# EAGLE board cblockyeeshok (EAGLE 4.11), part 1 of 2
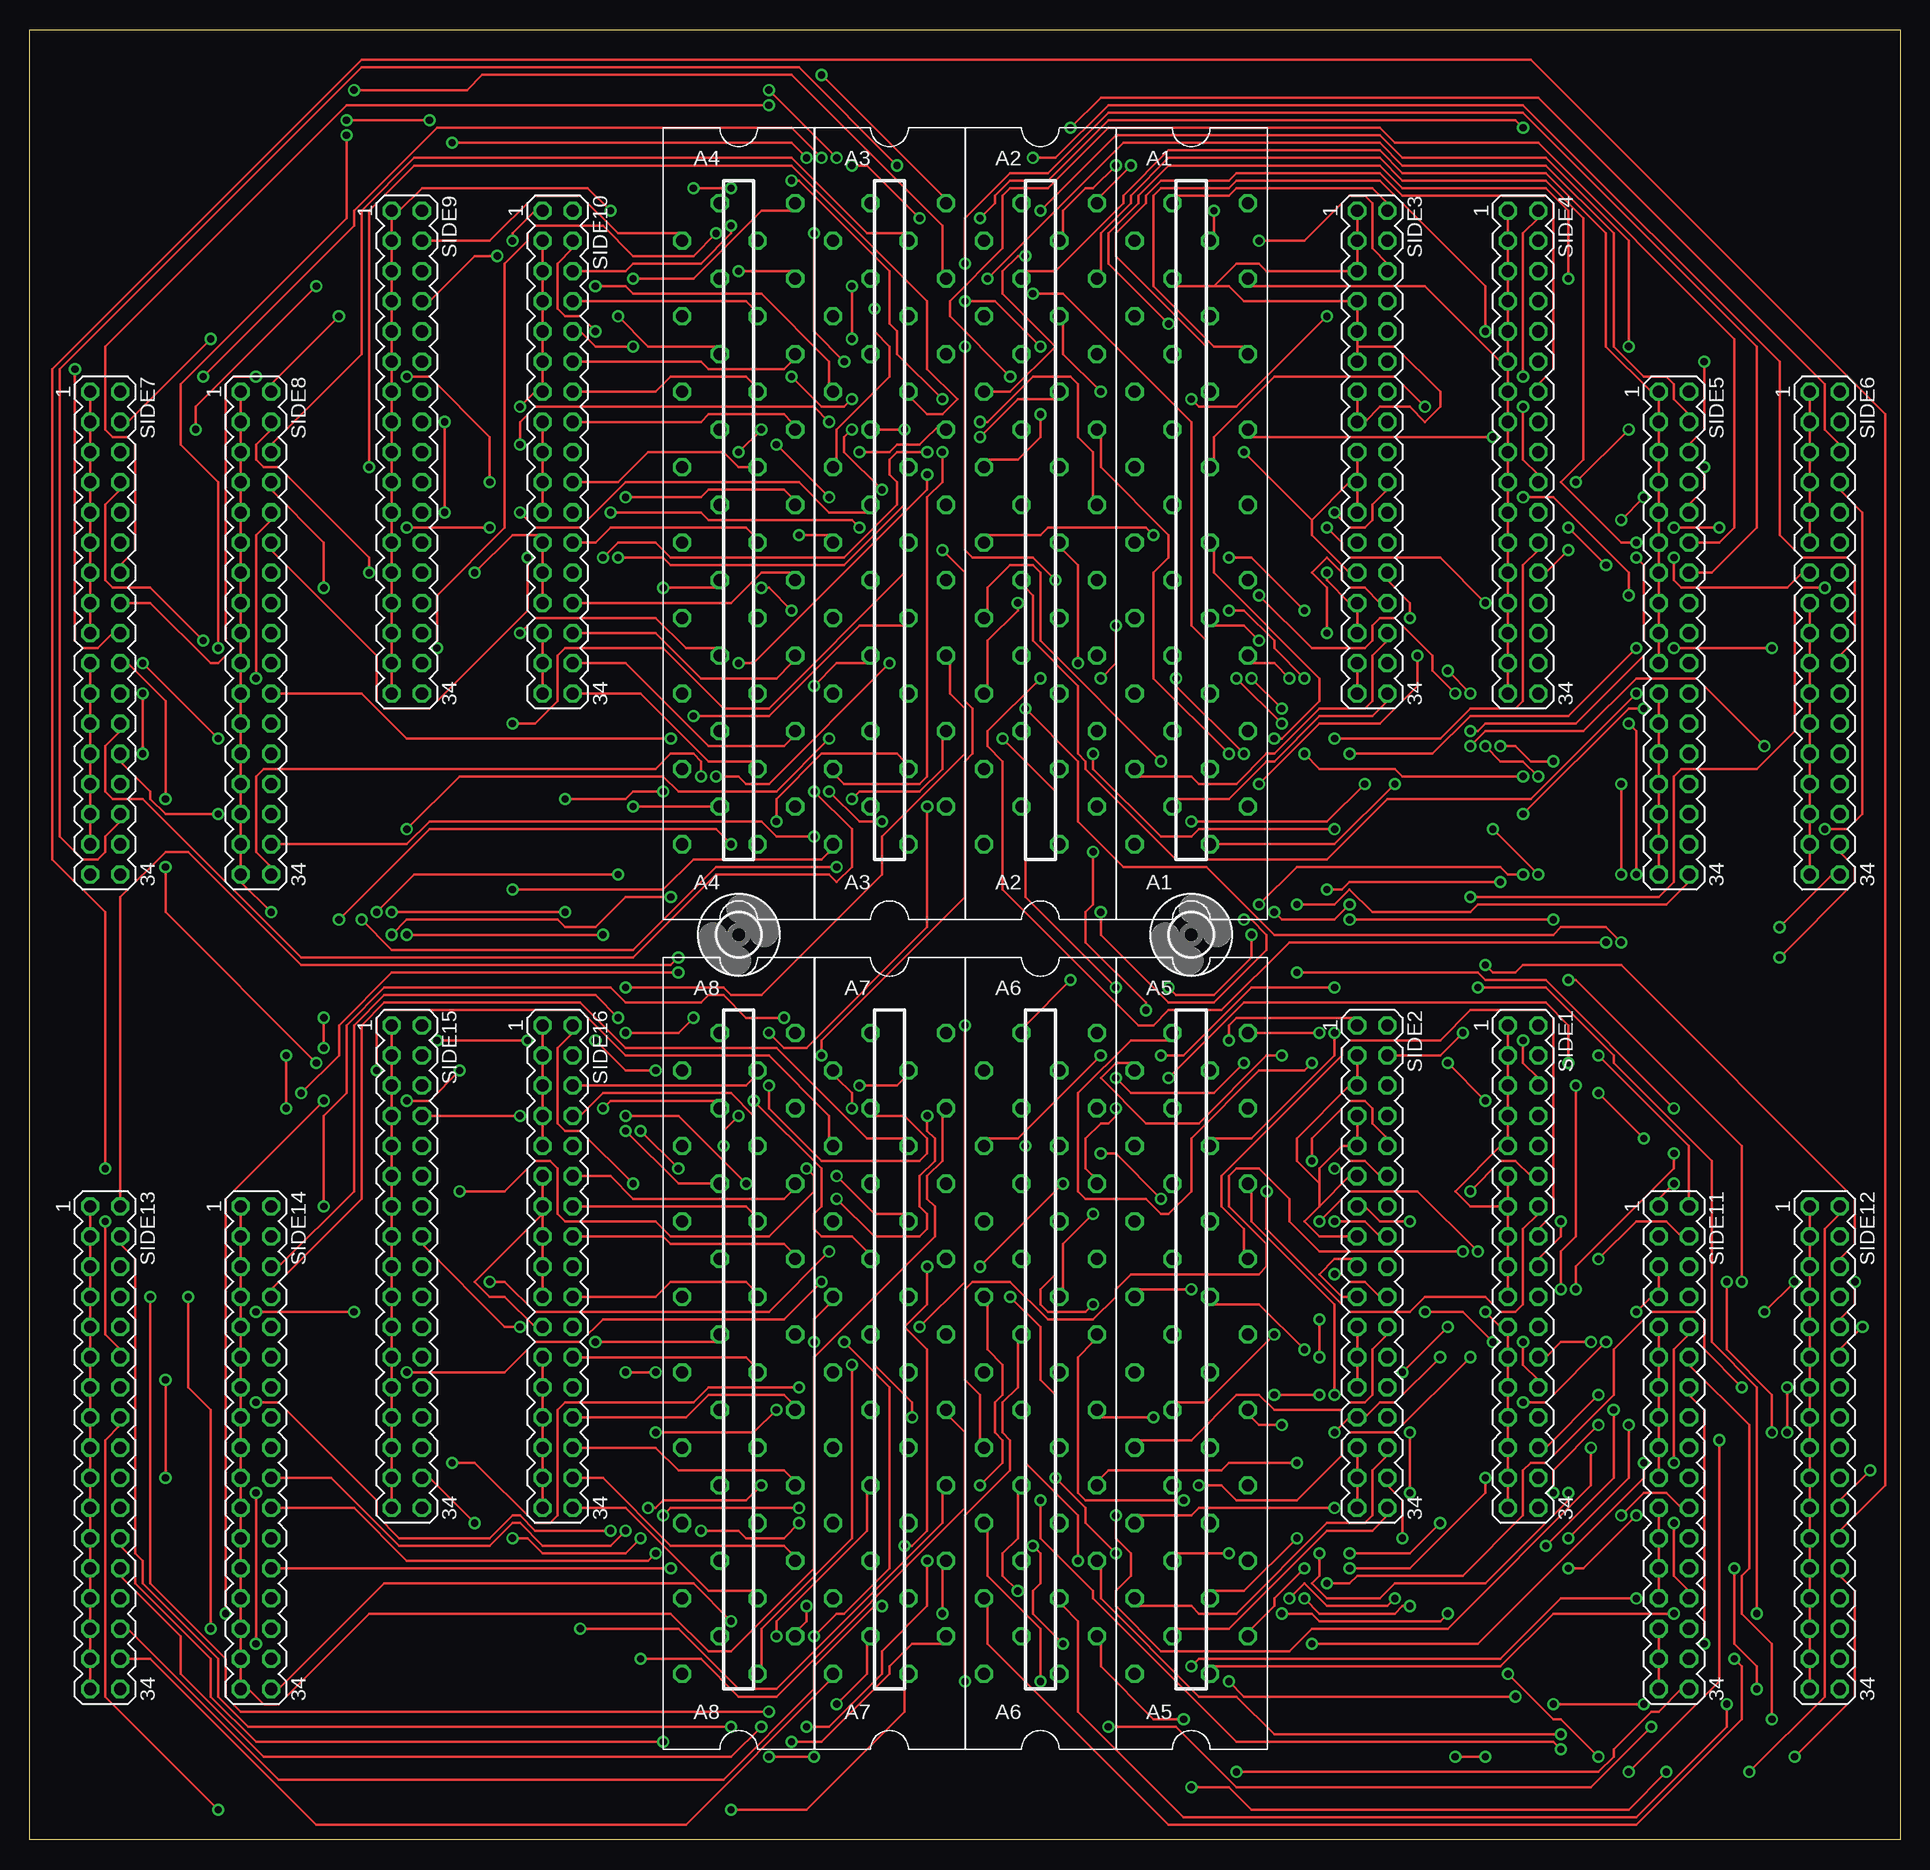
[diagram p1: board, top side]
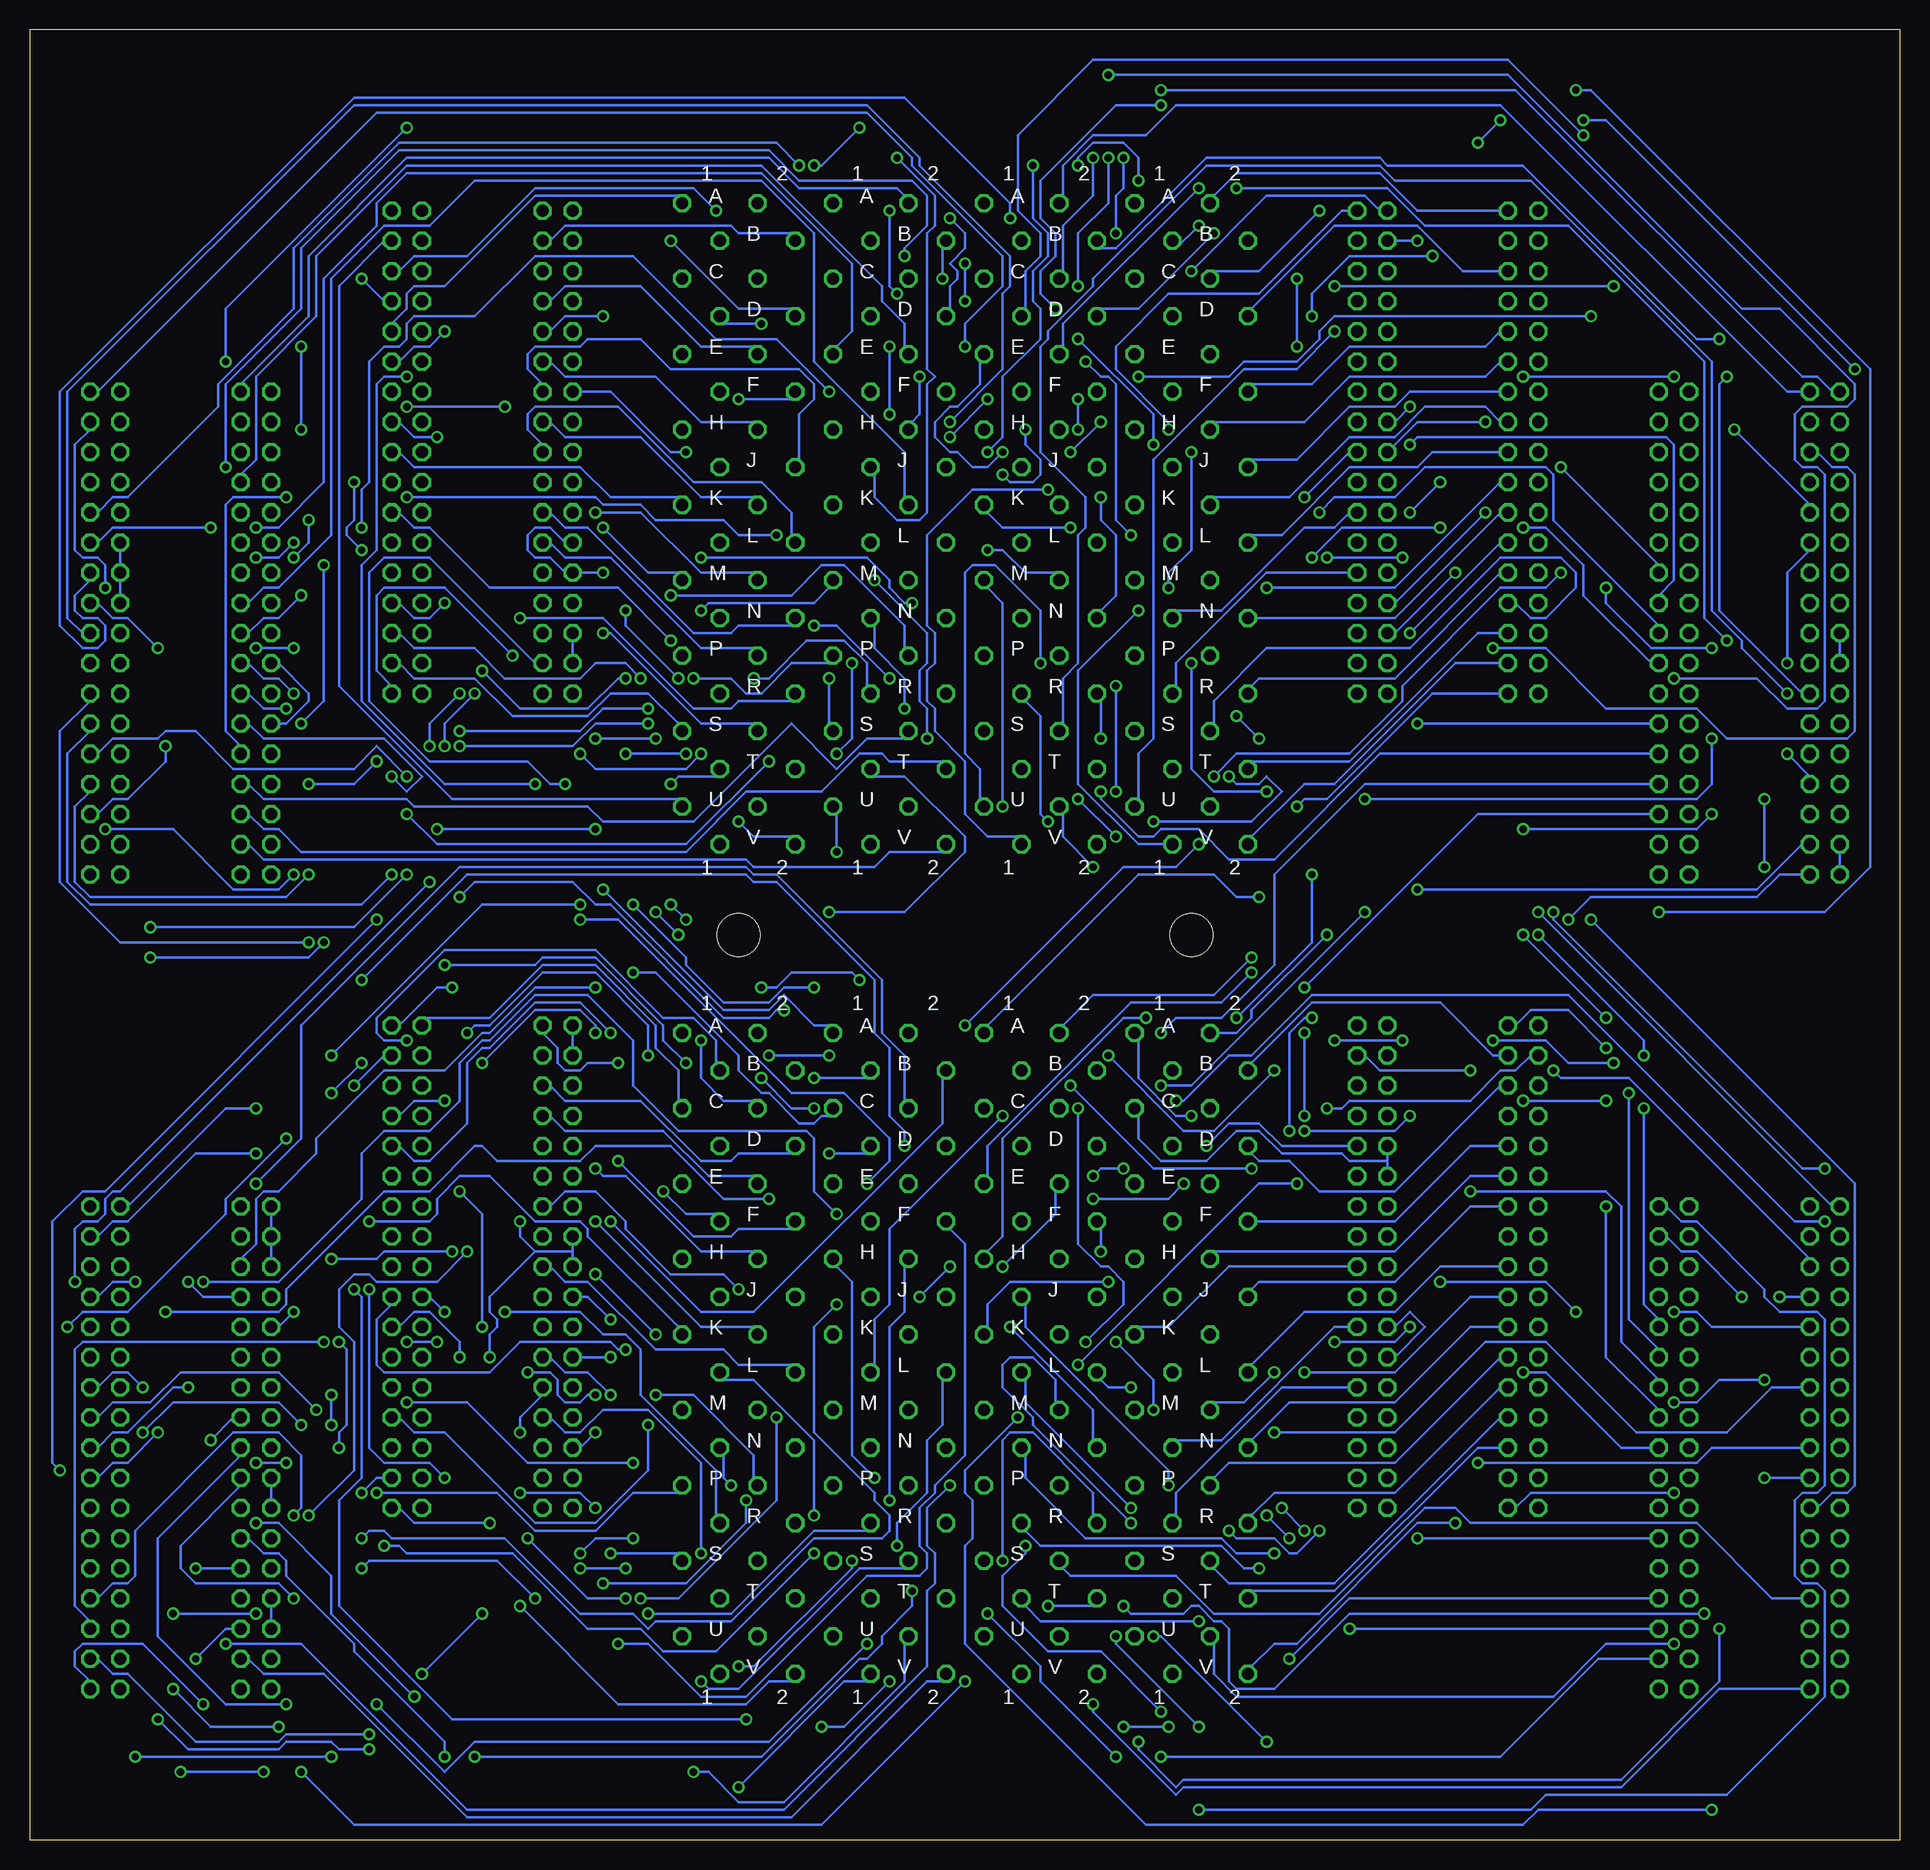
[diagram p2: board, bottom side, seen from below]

Size 157.48 x 152.4 mm. Coordinates in mm from the lower left corner, seen from the top.
Outline: 157.48,0 0,0 0,152.4 157.48,152.4 157.48,0
Copper layers (1*16): Top 0.035mm / dielectric 1.5mm / Bottom 0.035mm
Design rules "olimex8mil": minimum track width 8mil, minimum drill 24mil, track to track 8mil, track to pad 8mil, pad to pad 8mil, via to via 8mil, smd to smd 8mil, copper to edge 40mil, drill to drill 10mil, minimum pad ring 10mil, minimum via ring 8mil, stop-mask expansion 0mil, vias tented up to drill 0mil, thermal gap 10mil
Net classes: 1 Power: width 0.305 mm, drill 0.305 mm

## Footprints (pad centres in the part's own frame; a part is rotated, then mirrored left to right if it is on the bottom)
H807 = drill 1.016 octagon: A1 4.763,28.575; A2 -1.587,28.575; B1 1.587,25.4; B2 -4.763,25.4; C1 4.763,22.225; C2 -1.587,22.225; D1 1.587,19.05; D2 -4.763,19.05; E1 4.763,15.875; E2 -1.587,15.875; F1 1.587,12.7; F2 -4.763,12.7; H1 4.763,9.525; H2 -1.587,9.525; J1 1.587,6.35; J2 -4.763,6.35; K1 4.763,3.175; K2 -1.587,3.175; L1 1.587,0; L2 -4.763,0; M1 4.763,-3.175; M2 -1.587,-3.175; N1 1.587,-6.35; N2 -4.763,-6.35; P1 4.763,-9.525; P2 -1.587,-9.525; R1 1.587,-12.7; R2 -4.763,-12.7; S1 4.763,-15.875; S2 -1.587,-15.875; T1 1.587,-19.05; T2 -4.763,-19.05; U1 4.763,-22.225; U2 -1.587,-22.225; V1 1.587,-25.4; V2 -4.763,-25.4
MA17-2 = drill 1.016 octagon: 1 -20.32,-1.27; 2 -20.32,1.27; 3 -17.78,-1.27; 4 -17.78,1.27; 5 -15.24,-1.27; 6 -15.24,1.27; 7 -12.7,-1.27; 8 -12.7,1.27; 9 -10.16,-1.27; 10 -10.16,1.27; 11 -7.62,-1.27; 12 -7.62,1.27; 13 -5.08,-1.27; 14 -5.08,1.27; 15 -2.54,-1.27; 16 -2.54,1.27; 17 0,-1.27; 18 0,1.27; 19 2.54,-1.27; 20 2.54,1.27; 21 5.08,-1.27; 22 5.08,1.27; 23 7.62,-1.27; 24 7.62,1.27; 25 10.16,-1.27; 26 10.16,1.27; 27 12.7,-1.27; 28 12.7,1.27; 29 15.24,-1.27; 30 15.24,1.27; 31 17.78,-1.27; 32 17.78,1.27; 33 20.32,-1.27; 34 20.32,1.27
3,6 = hole 3.6: 0,0

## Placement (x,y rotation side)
A1  [H807]  97.79,109.22 0 top
A2  [H807]  85.09,109.22 0 top
A3  [H807]  72.39,109.22 0 top
A4  [H807]  59.69,109.22 0 top
A5  [H807]  97.79,39.37 0 top
A6  [H807]  85.09,39.37 0 top
A7  [H807]  72.39,39.37 0 top
A8  [H807]  59.69,39.37 0 top
SIDE1  [MA17-2]  125.73,48.26 270 top
SIDE2  [MA17-2]  113.03,48.26 270 top
SIDE3  [MA17-2]  113.03,116.84 270 top
SIDE4  [MA17-2]  125.73,116.84 270 top
SIDE5  [MA17-2]  138.43,101.6 270 top
SIDE6  [MA17-2]  151.13,101.6 270 top
SIDE7  [MA17-2]  6.35,101.6 270 top
SIDE8  [MA17-2]  19.05,101.6 270 top
SIDE9  [MA17-2]  31.75,116.84 270 top
SIDE10  [MA17-2]  44.45,116.84 270 top
SIDE11  [MA17-2]  138.43,33.02 270 top
SIDE12  [MA17-2]  151.13,33.02 270 top
SIDE13  [MA17-2]  6.35,33.02 270 top
SIDE14  [MA17-2]  19.05,33.02 270 top
SIDE15  [MA17-2]  31.75,48.26 270 top
SIDE16  [MA17-2]  44.45,48.26 270 top
U$5  [3,6]  59.69,76.2 0 top
U$6  [3,6]  97.79,76.2 0 top

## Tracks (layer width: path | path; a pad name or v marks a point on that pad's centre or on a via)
N$1  (via drill 0.61)
  Top 0.203: SIDE2.3 111.76,65.41 111.76,64.14 SIDE2.5 111.12,63.5 106.68,59.05 106.68,57.15 108.58,55.24 | v100.97,67.31 100.97,68.58 101.6,69.22 111.76,69.22 SIDE2.1 | SIDE2.33 111.76,28.57 111.76,29.84 SIDE2.31 111.76,31.11 111.76,32.38 SIDE2.29 | v109.86,34.29 111.12,35.56 SIDE2.27 112.39,35.56 113.67,36.83 114.94,36.83 v118.75,40.64 | SIDE2.25 111.76,38.73 111.76,40.01 SIDE2.23 111.76,41.27 111.76,42.55 SIDE2.21 | SIDE2.7 111.76,60.33 111.76,59.05 SIDE2.9 111.12,58.42 110.49,58.42 108.58,56.52 108.58,55.24 | SIDE2.19 111.12,45.72 110.49,45.72 108.58,47.62 109.86,48.9 111.76,48.9 SIDE2.17 | v116.2,52.07 113.67,52.07 112.39,53.34 SIDE2.13 | 108.58,53.34 107.31,52.07 108.58,50.8 111.12,50.8 SIDE2.15 | 108.58,53.34 111.12,55.88 SIDE2.11 | 108.58,53.34 108.58,55.24 | v108.58,43.81 v108.58,40.64
  Bottom 0.203: v100.97,67.31 100.97,64.14 99.06,62.23 96.52,62.23 A5.C2 | SIDE2.3 111.76,66.67 111.76,67.94 SIDE2.1 | v109.86,34.29 111.12,33.02 SIDE2.29 | 111.76,49.53 111.76,48.9 SIDE2.17 | 111.76,49.53 111.76,50.16 SIDE2.15 | v116.2,52.07 116.2,50.8 114.94,49.53 | 114.94,49.53 111.76,49.53 | v108.58,40.64 111.12,40.64 SIDE2.23 | v108.58,43.81 110.49,45.72 111.12,45.72 SIDE2.19 | v118.75,40.64 118.75,42.55 118.11,43.18 118.11,43.81 118.75,44.45 118.75,45.72 114.94,49.53
N$2  (via drill 0.61)
  Top 0.203: v107.95,65.41 107.31,64.77 103.5,64.77 97.79,59.05 97.79,54.61 95.89,52.7 95.25,52.7 93.98,53.98 88.9,53.98 88.27,54.61 88.27,62.87 92.71,67.31 95.89,67.31 A5.A2
  Bottom 0.203: v107.95,65.41 110.49,65.41 111.12,64.77 112.39,64.77 113.03,65.41 113.03,66.67 114.3,67.94 SIDE2.2
N$3  (via drill 0.61)
  Top 0.203: v105.41,66.04 104.14,66.04 98.42,60.33 93.98,60.33 90.17,64.14 91.44,65.41 92.71,65.41 A5.B2 | v120.65,67.94 118.75,66.04 114.94,66.04 SIDE2.4
  Bottom 0.203: v105.41,66.04 105.41,68.58 109.86,73.03 114.3,73.03 118.75,68.58 120.02,68.58 v120.65,67.94
N$4
  Bottom 0.203: A5.D2 93.34,57.78 97.79,57.78 98.42,57.15 100.97,57.15 106.05,62.23 112.39,62.23 113.67,63.5 SIDE2.6
N$5
  Bottom 0.203: A5.E2 96.52,55.88 100.33,55.88 104.14,59.69 112.39,59.69 113.67,60.96 SIDE2.8
N$6  (via drill 0.61)
  Top 0.203: v107.95,57.15 107.95,59.05 111.12,62.23 112.39,62.23 113.03,61.59 113.03,60.33 114.3,59.05 SIDE2.10
  Bottom 0.203: v107.95,57.15 101.6,50.8 98.42,50.8 97.79,51.44 93.34,51.44 A5.F2
N$7  (via drill 0.61)
  Top 0.203: v109.86,56.52 110.49,56.52 111.12,57.15 112.39,57.15 113.67,55.88 SIDE2.12
  Bottom 0.203: v109.86,56.52 109.22,55.88 107.31,55.88 100.97,49.53 96.52,49.53 A5.H2
N$8  (via drill 0.61)
  Top 0.203: v97.79,46.35 93.34,46.35 A5.J2
  Bottom 0.203: v97.79,46.35 99.06,47.62 103.5,47.62 107.31,51.44 107.31,52.07 109.86,54.61 112.39,54.61 113.67,53.34 SIDE2.14
N$9  (via drill 0.61)
  Top 0.203: v109.86,52.07 112.39,52.07 113.67,50.8 SIDE2.16
  Bottom 0.203: v109.86,52.07 100.97,43.18 96.52,43.18 A5.K2
N$10
  Bottom 0.203: A5.L2 93.34,40.01 97.79,40.01 99.06,41.27 104.78,41.27 110.49,46.99 112.39,46.99 113.67,48.26 SIDE2.18
N$11  (via drill 0.61)
  Top 0.203: v104.78,42.55 99.06,36.83 96.52,36.83 A5.M2 | v109.86,47.62 110.49,47.62 111.12,46.99 112.39,46.99 113.67,45.72 SIDE2.20
  Bottom 0.203: v104.78,42.55 v109.86,47.62
N$12
  Top 0.203: A5.N2 93.34,33.66 97.79,33.66 101.6,37.47 103.5,37.47 104.78,36.2 110.49,36.2 111.12,36.83 112.39,36.83 113.03,37.47 113.03,41.27 114.3,42.55 SIDE2.22
N$13  (via drill 0.61)
  Top 0.203: v104.78,37.47 v108.58,37.47
  Bottom 0.203: v104.78,37.47 101.6,37.47 96.52,32.38 96.52,30.48 A5.P2 | v108.58,37.47 110.49,39.37 112.39,39.37 113.67,40.64 SIDE2.24
N$14  (via drill 0.61)
  Top 0.203: v109.86,27.94 98.42,27.94 97.79,27.3 93.34,27.3 A5.R2 | v116.2,29.21 v116.2,34.29
  Bottom 0.203: v109.86,27.94 111.12,29.21 v116.2,29.21 | v116.2,34.29 116.2,35.56 114.3,37.47 SIDE2.26
N$15  (via drill 0.61)
  Top 0.203: v100.97,24.13 96.52,24.13 A5.S2
  Bottom 0.203: v100.97,24.13 100.97,31.75 105.41,36.2 109.22,36.2 111.12,34.29 112.39,34.29 113.67,35.56 SIDE2.28
N$16
  Top 0.203: A5.T2 93.34,19.68 97.79,19.68 98.42,19.05 101.6,19.05 109.22,26.67 112.39,26.67 113.03,27.3 113.03,31.11 114.3,32.38 SIDE2.30
N$17
  Top 0.203: A5.U2 96.52,17.78 100.97,17.78 109.22,26.04 113.03,26.04 114.3,27.3 SIDE2.34
N$18  (via drill 0.61)
  Top 0.203: v116.2,19.68 115.57,19.68 114.94,19.05 108.58,19.05 v107.31,20.32 | v115.57,25.4 115.57,28.57 114.3,29.84 SIDE2.32
  Bottom 0.203: v116.2,19.68 107.95,11.43 97.16,11.43 95.25,13.34 93.34,13.34 A5.V2 | v107.31,20.32 110.49,20.32 v115.57,25.4
N$19  (via drill 0.61)
  Top 0.203: v108.58,67.94 102.87,67.94 A5.A1
  Bottom 0.203: v108.58,67.94 111.12,70.48 114.94,70.48 118.75,66.67 119.38,66.67 120.65,65.41 120.65,60.33 123.83,57.15 125.09,57.15 126.36,58.42 SIDE1.10
N$20  (via drill 0.61)
  Top 0.203: v125.73,67.31 125.73,65.41 127,64.14 SIDE1.6
  Bottom 0.203: v125.73,67.31 127.64,67.31 128.27,67.94 128.27,69.22 122.56,74.93 109.86,74.93 104.14,69.22 101.6,69.22 99.69,67.31 99.69,65.41 A5.B1
N$21  (via drill 0.61)
  Top 0.203: v109.86,67.94 109.86,66.04 102.87,59.05 99.69,59.05 A5.D1 | v119.38,65.41 v122.56,62.23
  Bottom 0.203: v109.86,67.94 109.86,68.58 111.12,69.85 114.94,69.85 v119.38,65.41 | v122.56,62.23 125.09,62.23 126.36,60.96 SIDE1.8
N$22  (via drill 0.61)
  Top 0.203: v109.86,37.47 109.86,45.09 102.87,52.07 102.87,54.61 A5.E1 | v115.57,39.37 v119.38,43.18 | v121.28,54.61 123.83,57.15 125.09,57.15 126.36,55.88 SIDE1.12
  Bottom 0.203: v109.86,37.47 110.49,37.47 111.12,36.83 112.39,36.83 113.03,37.47 113.03,38.73 113.67,39.37 v115.57,39.37 | v119.38,43.18 119.38,52.7 v121.28,54.61
N$23  (via drill 0.61)
  Top 0.203: v104.14,54.61 104.14,51.44 111.12,44.45 116.2,44.45 117.47,45.72 122.56,45.72 123.83,44.45 125.09,44.45 125.73,45.09 125.73,51.44 127,52.7 SIDE1.14
  Bottom 0.203: v104.14,54.61 102.23,52.7 99.69,52.7 A5.F1
N$24
  Top 0.203: A5.H1 102.23,49.53 102.23,51.44 100.33,53.34 100.33,55.88 110.49,66.04 110.49,66.67 111.12,67.31 118.75,67.31 121.28,69.85 127.64,69.85 128.27,69.22 128.27,52.7 127,51.44 SIDE1.16
N$25  (via drill 0.61)
  Top 0.203: v107.31,41.27 103.5,45.09 99.69,45.09 A5.J1
  Bottom 0.203: v107.31,41.27 107.95,41.27 108.58,41.91 116.2,41.91 118.75,39.37 127.64,39.37 128.27,40.01 128.27,43.81 127,45.09 SIDE1.20
N$26  (via drill 0.61)
  Top 0.203: v128.91,52.07 128.91,50.8 127,48.9 SIDE1.18
  Bottom 0.203: v128.91,52.07 123.83,52.07 123.19,52.7 123.19,53.98 121.28,55.88 118.75,55.88 114.94,52.07 111.12,52.07 110.49,51.44 110.49,50.8 102.87,43.18 A5.K1
N$27  (via drill 0.61)
  Top 0.203: v91.44,27.3 91.44,25.4 92.71,24.13 92.71,22.23 91.44,20.95 91.44,19.68 95.25,15.88 106.05,15.88 107.95,17.78 119.38,17.78 131.44,29.84 v131.44,33.02 | v131.44,41.91 128.91,41.91 127.64,40.64 SIDE1.24
  Bottom 0.203: v91.44,27.3 91.44,33.66 96.52,38.73 99.06,38.73 A5.L1 | v131.44,33.02 131.44,34.29 130.81,34.92 130.81,41.27 v131.44,41.91
N$28  (via drill 0.61)
  Top 0.203: v105.41,34.92 103.5,34.92 102.87,35.56 A5.M1
  Bottom 0.203: v105.41,34.92 105.41,31.11 109.86,26.67 114.94,26.67 122.56,34.29 125.09,34.29 126.36,35.56 SIDE1.28
N$29  (via drill 0.61)
  Top 0.203: v98.42,29.84 100.33,29.84 101.6,28.57 106.68,28.57 110.49,32.38 110.49,33.66 111.12,34.29 114.94,34.29 v121.28,40.64
  Bottom 0.203: v98.42,29.84 99.06,30.48 99.06,32.38 A5.N1 | v121.28,40.64 121.28,41.91 123.83,44.45 125.09,44.45 126.36,43.18 SIDE1.22
N$30  (via drill 0.61)
  Top 0.203: v128.27,29.21 128.27,31.11 v132.08,34.92 | v132.08,37.47 127.64,33.02 SIDE1.30
  Bottom 0.203: v128.27,29.21 118.11,29.21 114.94,26.04 109.86,26.04 106.68,29.21 102.87,29.21 A5.P1 | v132.08,34.92 v132.08,37.47
N$31  (via drill 0.61)
  Top 0.203: v117.47,44.45 120.65,44.45 v123.19,41.91 | v125.73,41.91 125.73,40.01 127,38.73 SIDE1.26
  Bottom 0.203: v117.47,44.45 111.12,44.45 109.22,42.55 107.31,42.55 106.05,41.27 106.05,37.47 99.69,31.11 99.69,27.3 A5.R1 | v123.19,41.91 v125.73,41.91
N$32  (via drill 0.61)
  Top 0.203: v108.58,24.13 108.58,22.23 107.95,21.59 109.22,20.32 113.67,20.32 114.94,21.59 122.56,21.59 129.54,28.57 v129.54,29.21
  Bottom 0.203: v108.58,24.13 102.87,24.13 A5.S1 | v129.54,29.21 128.27,30.48 127.64,30.48 SIDE1.32
N$33  (via drill 0.61)
  Top 0.203: v106.68,25.4 102.23,20.95 99.69,20.95 A5.T1 | v111.12,24.13 116.2,24.13 v118.75,26.67
  Bottom 0.203: v106.68,25.4 109.86,25.4 v111.12,24.13 | v118.75,26.67 125.09,26.67 126.36,27.94 SIDE1.34
N$34  (via drill 0.61)
  Top 0.203: v107.31,22.86 104.78,20.32 104.78,19.68 102.87,17.78 A5.U1 | v111.12,22.86 116.2,22.86 122.56,29.21 v122.56,30.48 | v128.91,46.35 128.91,49.53 130.18,50.8 v130.18,63.5
  Bottom 0.203: v107.31,22.86 v111.12,22.86 | v122.56,30.48 123.83,31.75 127.64,31.75 128.91,33.02 v128.91,46.35 | v130.18,63.5 127.64,66.04 SIDE1.4
N$35  (via drill 0.61)
  Top 0.203: v138.43,19.05 128.27,19.05 123.83,14.61 99.69,14.61 A5.V1 | v145.41,19.05 145.41,38.1 141.6,41.91 141.6,57.15 133.35,65.41 133.35,66.04 127.64,71.75 v121.92,71.75
  Bottom 0.203: v138.43,19.05 v145.41,19.05 | v121.92,71.75 123.19,71.75 126.36,68.58 SIDE1.2
N$36  (via drill 0.61)
  Top 0.203: SIDE1.33 124.46,28.57 124.46,29.84 SIDE1.31 124.46,31.11 124.46,32.38 SIDE1.29 124.46,33.66 124.46,34.92 SIDE1.27 124.46,36.2 124.46,37.47 SIDE1.25 124.46,38.73 124.46,40.01 SIDE1.23 124.46,41.27 124.46,42.55 SIDE1.21 123.83,43.18 v122.56,44.45 | SIDE1.19 124.46,46.35 124.46,47.62 SIDE1.17 124.46,48.9 124.46,50.16 SIDE1.15 124.46,51.44 124.46,52.7 SIDE1.13 | SIDE1.11 124.46,55.24 124.46,53.98 SIDE1.13 | SIDE1.1 124.46,67.94 124.46,66.67 SIDE1.3 124.46,65.41 124.46,64.14 SIDE1.5 124.46,62.87 124.46,61.59 SIDE1.7 124.46,60.33 124.46,59.05 SIDE1.9 123.83,58.42 120.02,54.61 121.28,53.34 123.83,53.34 SIDE1.13
  Bottom 0.203: A5.C1 102.87,62.23 102.87,64.77 104.78,66.67 104.78,68.58 109.86,73.66 114.3,73.66 118.75,69.22 124.46,69.22 SIDE1.1 | v122.56,44.45 123.83,45.72 SIDE1.19
N$37  (via drill 0.61)
  Top 0.203: SIDE3.33 111.76,97.16 111.76,98.42 SIDE3.31 | SIDE3.29 111.76,102.23 111.76,103.5 SIDE3.27 111.12,104.14 109.22,106.05 v109.22,106.68 | 107.95,111.12 107.95,109.86 111.12,106.68 SIDE3.25 | 107.95,111.12 111.12,114.3 SIDE3.19 | SIDE3.21 111.76,112.39 111.76,113.67 SIDE3.19 | SIDE3.17 111.76,116.2 111.76,114.94 SIDE3.19 | SIDE3.13 111.76,121.28 111.76,120.02 SIDE3.15 112.39,119.38 113.67,120.65 116.2,120.65 117.47,119.38 118.75,120.65 118.75,121.92 114.94,125.73 111.76,125.73 | 111.76,125.73 111.76,126.36 SIDE3.9 111.76,127.64 111.76,128.91 SIDE3.7 111.12,129.54 102.23,129.54 100.97,130.81 99.69,130.81 | 111.76,125.73 111.76,125.09 SIDE3.11 | SIDE3.1 111.76,136.53 111.76,135.25 SIDE3.3 111.76,133.99 111.76,132.72 SIDE3.5 111.12,132.08 104.14,132.08 103.5,132.72 101.6,132.72 99.69,130.81 | 99.69,130.81 96.52,130.81 A1.C2 | 107.95,111.12 v102.23,116.84
  Bottom 0.203: SIDE3.29 111.76,100.97 111.76,99.69 SIDE3.31 | SIDE3.23 112.39,109.22 113.67,110.49 114.94,110.49 115.57,109.86 115.57,108.58 114.94,107.95 113.67,107.95 112.39,106.68 SIDE3.25 111.12,106.68 v109.22,106.68 | v102.23,116.84 103.5,116.84 108.58,121.92 111.12,121.92 SIDE3.13
N$38
  Top 0.203: SIDE3.2 114.3,137.79 113.03,139.06 101.6,139.06 100.97,138.43 96.52,138.43 A1.A2
N$39
  Bottom 0.203: A1.B2 93.34,135.25 97.79,135.25 98.42,135.89 112.39,135.89 113.67,134.62 SIDE3.4
N$40  (via drill 0.61)
  Top 0.203: v103.5,134.62 107.31,134.62 111.12,138.43 112.39,138.43 113.03,137.79 113.03,133.99 114.3,132.72 SIDE3.6
  Bottom 0.203: v103.5,134.62 97.79,128.91 93.34,128.91 A1.D2
N$41
  Bottom 0.203: A1.E2 96.52,125.73 100.97,125.73 106.05,130.81 112.39,130.81 113.67,129.54 SIDE3.8
N$42  (via drill 0.61)
  Top 0.203: v97.79,121.28 98.42,120.65 101.6,120.65 v109.22,128.27
  Bottom 0.203: v97.79,121.28 93.34,121.28 A1.F2 | v109.22,128.27 112.39,128.27 113.67,127 SIDE3.10
N$43
  Bottom 0.203: A1.H2 96.52,119.38 100.97,119.38 104.78,123.19 112.39,123.19 113.67,124.46 SIDE3.12
N$44
  Bottom 0.203: A1.J2 92.71,116.2 92.71,120.02 91.44,121.28 91.44,122.56 92.71,123.83 103.5,123.83 106.05,126.36 110.49,126.36 111.12,125.73 114.94,125.73 115.57,125.09 115.57,123.83 114.3,122.56 SIDE3.14
N$45
  Bottom 0.203: A1.K2 96.52,113.03 100.97,113.03 106.05,118.11 112.39,118.11 113.67,119.38 SIDE3.16
N$46
  Bottom 0.203: A1.L2 93.34,109.86 93.34,111.76 95.89,114.3 101.6,114.3 107.95,120.65 114.94,120.65 115.57,120.02 115.57,118.75 114.3,117.47 SIDE3.18
N$47  (via drill 0.61)
  Top 0.203: v109.86,111.76 111.12,110.49 112.39,110.49 113.03,111.12 113.03,112.39 114.3,113.67 SIDE3.20
  Bottom 0.203: v109.86,111.76 106.05,111.76 100.97,106.68 96.52,106.68 A1.M2
N$48
  Bottom 0.203: A1.N2 93.34,102.23 97.79,102.23 98.42,101.6 101.6,101.6 110.49,110.49 112.39,110.49 113.67,111.76 SIDE3.22
N$49
  Bottom 0.203: A1.P2 96.52,100.33 100.97,100.33 108.58,107.95 112.39,107.95 113.67,109.22 SIDE3.24
N$50  (via drill 0.61)
  Top 0.203: v116.2,102.87 116.2,104.14 114.3,106.05 SIDE3.26
  Bottom 0.203: v116.2,102.87 109.22,102.87 101.6,95.25 98.42,95.25 97.79,95.89 93.34,95.89 A1.R2
N$51  (via drill 0.61)
  Top 0.203: v109.22,101.6 109.22,105.41 107.95,106.68 109.22,107.95 110.49,106.68 110.49,106.05 111.12,105.41 112.39,105.41 113.67,104.14 SIDE3.28
  Bottom 0.203: v109.22,101.6 108.58,101.6 100.97,93.98 96.52,93.98 A1.S2
N$52
  Top 0.203: A1.T2 93.34,89.53 97.79,89.53 98.42,88.9 101.6,88.9 104.14,91.44 104.78,91.44 108.58,95.25 112.39,95.25 113.03,95.89 113.03,99.69 114.3,100.97 SIDE3.30
N$53
  Top 0.203: A1.U2 96.52,87.63 100.97,87.63 104.14,90.81 104.78,90.81 108.58,94.61 113.03,94.61 114.3,95.89 SIDE3.34
N$54  (via drill 0.61)
  Top 0.203: v97.79,85.72 109.22,85.72 v112.39,88.9
  Bottom 0.203: v97.79,85.72 96.52,84.45 93.34,84.45 A1.V2 | v112.39,88.9 113.67,88.9 115.57,90.81 123.83,90.81 128.91,95.89 128.91,106.68 127.64,107.95 123.83,107.95 114.94,99.06 SIDE3.32
N$55
  Bottom 0.203: SIDE4.10 127,127.64 125.73,128.91 125.73,130.18 125.09,130.81 122.56,130.81 114.94,138.43 102.87,138.43 A1.A1
N$56  (via drill 0.61)
  Top 0.203: v99.69,137.16 99.69,135.25 A1.B1
  Bottom 0.203: v99.69,137.16 101.6,139.06 114.94,139.06 120.65,133.35 125.09,133.35 126.36,132.08 SIDE4.6
N$57  (via drill 0.61)
  Top 0.203: v95.89,127.64 90.81,132.72 90.81,135.25 93.34,137.79 93.34,138.43 95.89,140.97 113.67,140.97 115.57,139.06 127.64,139.06 129.54,137.16 v129.54,131.44
  Bottom 0.203: v95.89,127.64 99.06,127.64 A1.D1 | v129.54,131.44 127.64,129.54 SIDE4.8
N$58  (via drill 0.61)
  Top 0.203: v122.56,127 122.56,130.81 113.67,139.7 101.6,139.7 100.97,139.06 95.25,139.06 94.61,138.43 94.61,130.81 99.69,125.73 102.23,125.73 A1.E1
  Bottom 0.203: v122.56,127 123.83,125.73 125.09,125.73 126.36,124.46 SIDE4.12
N$59
  Top 0.203: A1.F1 99.06,122.56 99.06,125.73 91.44,133.35 91.44,135.25 93.98,137.79 93.98,138.43 95.25,139.7 100.97,139.7 101.6,140.34 113.67,140.34 115.57,138.43 127.64,138.43 128.27,137.79 128.27,123.83 127,122.56 SIDE4.14
N$60  (via drill 0.61)
  Top 0.203: v123.19,118.11 102.87,118.11 A1.H1
  Bottom 0.203: v123.19,118.11 125.09,118.11 126.36,119.38 SIDE4.16
N$61  (via drill 0.61)
  Top 0.203: v125.73,120.65 125.73,116.2 127,114.94 SIDE4.20 | v117.47,120.65 114.94,123.19 104.78,123.19 99.69,118.11 99.69,116.2 A1.J1
  Bottom 0.203: v117.47,120.65 v125.73,120.65
N$62
  Bottom 0.203: A1.K1 102.87,113.03 108.58,113.03 111.12,115.57 125.09,115.57 126.36,116.84 SIDE4.18
N$63  (via drill 0.61)
  Top 0.203: v104.78,92.71 105.41,92.71 108.58,95.89 108.58,97.79 99.69,106.68 99.69,108.58 A1.L1 | v109.86,92.71 118.75,92.71 121.28,95.25 125.09,95.25 125.73,95.89 125.73,107.31 127,108.58 SIDE4.24
  Bottom 0.203: v104.78,92.71 v109.86,92.71
N$64  (via drill 0.61)
  Top 0.203: v109.22,110.49 110.49,109.22 110.49,108.58 111.12,107.95 118.75,107.95 v122.56,104.14
  Bottom 0.203: v109.22,110.49 105.41,106.68 102.87,106.68 A1.M1 | v122.56,104.14 123.83,102.87 125.09,102.87 126.36,104.14 SIDE4.28
N$65  (via drill 0.61)
  Top 0.203: v103.5,100.97 102.23,102.23 99.69,102.23 A1.N1
  Bottom 0.203: v103.5,100.97 107.95,105.41 118.75,105.41 123.83,110.49 125.09,110.49 126.36,111.76 SIDE4.22
N$66  (via drill 0.61)
  Top 0.203: v106.05,97.79 104.78,99.06 102.87,99.06 A1.P1
  Bottom 0.203: v106.05,97.79 107.31,99.06 109.86,99.06 111.12,97.79 117.47,97.79 120.02,100.33 125.09,100.33 126.36,101.6 SIDE4.30
N$67  (via drill 0.61)
  Top 0.203: v84.45,130.18 87,130.18 97.79,119.38 97.79,102.23 99.06,100.97 99.06,97.16 A1.R1 | v85.09,137.16 91.44,143.51 113.67,143.51 115.57,141.6 127.64,141.6 134.62,134.62 v134.62,125.73 | v134.62,118.75 v130.18,114.3 | v129.54,108.58 127.64,106.68 SIDE4.26
  Bottom 0.203: v84.45,130.18 85.09,130.81 v85.09,137.16 | v134.62,125.73 v134.62,118.75 | v130.18,114.3 130.18,111.12 130.81,110.49 130.81,109.86 v129.54,108.58
N$68
  Bottom 0.203: A1.S1 102.87,93.98 105.41,96.52 108.58,96.52 110.49,94.61 116.84,94.61 120.02,97.79 125.09,97.79 126.36,99.06 SIDE4.32
N$69  (via drill 0.61)
  Top 0.203: v103.5,88.9 108.58,93.98 113.67,93.98 116.84,97.16 v116.84,99.69
  Bottom 0.203: v103.5,88.9 102.87,89.53 99.69,89.53 A1.T1 | v116.84,99.69 122.56,105.41 127.64,105.41 128.27,104.78 128.27,98.42 127,97.16 SIDE4.34
N$70
  Bottom 0.203: A1.U1 102.87,87.63 121.92,87.63 131.44,97.16 131.44,130.81 127.64,134.62 SIDE4.4
N$71  (via drill 0.61)
  Top 0.203: v114.94,88.9 109.86,83.82 99.69,83.82 A1.V1 | v125.73,123.19 125.73,135.25 127,136.53 SIDE4.2
  Bottom 0.203: v114.94,88.9 122.56,88.9 129.54,95.89 129.54,107.31 128.27,108.58 128.27,122.56 127.64,123.19 v125.73,123.19
N$72
  Top 0.203: SIDE4.33 124.46,97.16 124.46,98.42 SIDE4.31 124.46,99.69 124.46,100.97 SIDE4.29 124.46,102.23 124.46,103.5 SIDE4.27 124.46,104.78 124.46,106.05 SIDE4.25 124.46,107.31 124.46,108.58 SIDE4.23 124.46,109.86 124.46,111.12 SIDE4.21 124.46,112.39 124.46,113.67 SIDE4.19 124.46,114.94 124.46,116.2 SIDE4.17 124.46,117.47 124.46,118.75 SIDE4.15 124.46,120.02 124.46,121.28 SIDE4.13 124.46,122.56 124.46,123.83 SIDE4.11 | SIDE4.11 124.46,125.09 124.46,126.36 SIDE4.9 124.46,127.64 124.46,128.91 SIDE4.7 124.46,130.18 124.46,131.44 SIDE4.5 124.46,132.72 124.46,133.99 SIDE4.3 124.46,135.25 124.46,136.53 SIDE4.1 | A1.C1 102.87,130.81 117.47,130.81 123.83,124.46 SIDE4.11
N$73
  Top 0.203: SIDE5.33 137.16,81.92 137.16,83.19 SIDE5.31 137.16,84.45 137.16,85.72 SIDE5.29 137.16,87 137.16,88.27 SIDE5.27 137.16,89.53 137.16,90.81 SIDE5.25 137.16,92.08 137.16,93.34 SIDE5.23 137.16,94.61 137.16,95.89 SIDE5.21 | SIDE5.19 137.16,99.69 137.16,100.97 SIDE5.17 137.16,102.23 137.16,103.5 SIDE5.15 137.16,104.78 137.16,106.05 SIDE5.13 137.16,107.31 137.16,108.58 SIDE5.11 137.16,109.86 137.16,111.12 SIDE5.9 137.16,112.39 137.16,113.67 SIDE5.7 137.16,114.94 137.16,116.2 SIDE5.5 137.16,117.47 137.16,118.75 SIDE5.3 137.16,120.02 137.16,121.28 SIDE5.1 136.53,121.92 132.72,125.73 132.72,135.25 127.64,140.34 115.57,140.34 113.67,142.24 95.89,142.24 92.08,138.43 92.08,137.79 86.36,132.08 83.82,132.08 A2.C2
  Bottom 0.203: SIDE5.23 136.53,93.98 135.89,93.98 133.99,95.89 133.99,96.52 136.53,99.06 SIDE5.19
N$74
  Bottom 0.203: SIDE5.2 139.7,122.56 133.99,128.27 133.99,133.35 125.73,141.6 95.25,141.6 92.71,139.06 84.45,139.06 83.82,138.43 A2.A2
N$75  (via drill 0.61)
  Top 0.203: v80.64,131.44 92.08,142.88 113.67,142.88 115.57,140.97 127.64,140.97 133.35,135.25 133.35,125.73 135.89,123.19 137.79,123.19 138.43,122.56 138.43,121.28 139.7,120.02 SIDE5.4
  Bottom 0.203: v80.64,131.44 80.64,133.99 A2.B2
N$76  (via drill 0.61)
  Top 0.203: v80.01,136.53 81.28,137.79 81.28,138.43 82.55,139.7 85.72,139.7 90.81,144.78 125.09,144.78 v125.73,144.15 | v140.97,124.46 140.97,118.75 139.7,117.47 SIDE5.6
  Bottom 0.203: v80.01,136.53 78.74,135.25 78.74,133.99 80.01,132.72 79.38,132.08 79.38,131.44 80.01,130.81 80.01,128.91 A2.D2 | v125.73,144.15 140.97,128.91 v140.97,124.46
N$77
  Bottom 0.203: SIDE5.8 139.7,114.94 138.43,116.2 138.43,123.19 133.35,128.27 133.35,133.35 125.73,140.97 95.89,140.97 85.72,130.81 85.72,129.54 83.82,127.64 83.82,125.73 A2.E2
N$78  (via drill 0.61)
  Top 0.203: v140.97,115.57 140.97,113.67 139.7,112.39 SIDE5.10 | v83.82,133.35 83.19,133.35 81.92,132.08 81.92,130.18 86.36,125.73 82.55,121.92 80.64,121.92 A2.F2
  Bottom 0.203: v140.97,115.57 140.97,122.56 134.62,128.91 134.62,133.99 126.36,142.24 95.25,142.24 92.71,139.7 83.19,139.7 81.92,138.43 81.92,135.89 83.82,133.99 v83.82,133.35
N$79  (via drill 0.61)
  Top 0.203: v82.55,123.19 77.47,128.27 77.47,129.54 81.92,133.99 81.92,138.43 82.55,139.06 85.72,139.06 90.81,144.15 113.67,144.15 114.94,142.88 127,142.88 143.51,126.36 143.51,110.49 142.24,109.22 140.34,109.22 SIDE5.12
  Bottom 0.203: v82.55,123.19 82.55,120.02 83.19,119.38 A2.H2
N$80  (via drill 0.61)
  Top 0.203: v85.09,120.02 85.09,118.11 83.19,116.2 80.64,116.2 A2.J2 | v85.09,125.73 81.28,129.54 v78.74,129.54 | v78.74,132.72 78.74,136.53 82.55,140.34 85.72,140.34 90.81,145.41 125.73,145.41 145.41,125.73 145.41,110.49 141.6,106.68 140.34,106.68 SIDE5.14
  Bottom 0.203: v85.09,125.73 v85.09,120.02 | v78.74,132.72 v78.74,129.54
N$81
  Bottom 0.203: A2.K2 83.82,113.03 83.82,116.84 91.44,124.46 91.44,135.25 95.89,139.7 120.02,139.7 123.83,135.89 127.64,135.89 132.08,131.44 132.08,109.86 136.53,105.41 137.79,105.41 139.06,104.14 SIDE5.16
N$82  (via drill 0.61)
  Top 0.203: v94.61,109.86 93.98,110.49 85.72,110.49 85.09,109.86 80.64,109.86 A2.L2 | v125.73,113.03 128.27,113.03 134.62,106.68 v134.62,104.78
  Bottom 0.203: v94.61,109.86 97.79,109.86 99.06,111.12 104.78,111.12 106.05,112.39 109.22,112.39 109.86,113.03 v125.73,113.03 | v134.62,104.78 136.53,102.87 137.79,102.87 139.06,101.6 SIDE5.18
N$83  (via drill 0.61)
  Top 0.203: v135.25,96.52 126.36,87.63 114.3,87.63 109.22,82.55 96.52,82.55 88.9,90.17 88.9,90.81 88.27,91.44 88.27,97.16 84.45,100.97 84.45,104.78 83.82,105.41 A2.M2
  Bottom 0.203: v135.25,96.52 136.53,97.79 137.79,97.79 139.06,99.06 SIDE5.20
N$84  (via drill 0.61)
  Top 0.203: v95.25,90.81 85.09,100.97 85.09,106.68 84.45,107.31 82.55,107.31 80.64,105.41 80.64,103.5 A2.N2 | v125.73,86.36 134.62,95.25 v135.89,95.25
  Bottom 0.203: v95.25,90.81 102.23,83.82 123.19,83.82 v125.73,86.36 | v135.89,95.25 137.79,95.25 139.06,96.52 SIDE5.22
N$85  (via drill 0.61)
  Top 0.203: v127,89.53 125.73,90.81 123.83,90.81 v122.56,92.08 | v120.02,96.52 118.11,98.42 118.11,99.69 114.94,102.87 113.67,102.87 113.03,102.23 113.03,100.97 112.39,100.33 107.95,100.33 v103.5,104.78
  Bottom 0.203: v127,89.53 125.73,88.27 124.46,89.53 127.64,92.71 137.79,92.71 139.06,93.98 SIDE5.24 | v122.56,92.08 122.56,93.98 v120.02,96.52 | v103.5,104.78 93.34,104.78 90.81,107.31 88.9,107.31 83.82,102.23 83.82,100.33 A2.P2
N$86  (via drill 0.61)
  Top 0.203: v83.19,104.14 83.19,103.5 80.64,100.97 80.64,97.16 A2.R2 | v100.97,107.95 102.87,107.95 v107.31,103.5 | v102.87,97.79 v105.41,95.25 | v121.28,93.34 121.92,93.34 122.56,93.98 130.18,93.98 136.53,100.33 135.89,100.97 135.89,107.31 v135.25,107.95 | v133.99,111.12 v135.89,113.03
  Bottom 0.203: v83.19,104.14 83.82,104.14 85.09,105.41 85.09,106.05 87,107.95 v100.97,107.95 | v107.31,103.5 107.31,102.23 v102.87,97.79 | v105.41,95.25 109.22,95.25 111.12,93.34 v121.28,93.34 | v135.25,107.95 133.99,109.22 v133.99,111.12 | v135.89,113.03 140.34,113.03 140.97,112.39 140.97,93.34 139.7,92.08 SIDE5.26
N$87
  Bottom 0.203: A2.S2 83.82,92.71 87,92.71 89.53,90.17 93.34,93.98 101.6,85.72 109.22,85.72 110.49,87 125.09,87 125.73,87.63 137.79,87.63 139.06,88.9 SIDE5.28
N$88
  Bottom 0.203: A2.T2 80.64,90.81 85.09,90.81 85.72,91.44 87.63,91.44 90.81,88.27 97.16,88.27 102.23,83.19 134.62,83.19 136.53,85.09 137.79,85.09 139.06,86.36 SIDE5.30
N$89  (via drill 0.61)
  Top 0.203: v106.68,78.74 109.86,78.74 111.12,80.01 113.03,78.11 121.28,78.11 121.92,78.74 137.79,78.74 139.7,80.64 SIDE5.34 | v91.44,71.75 83.82,79.38 83.82,86.36 A2.U2
  Bottom 0.203: v106.68,78.74 102.23,74.3 102.23,73.66 99.06,70.48 95.25,70.48 93.98,71.75 v91.44,71.75
N$90
  Bottom 0.203: A2.V2 80.64,83.19 85.09,83.19 86.36,81.92 96.52,81.92 97.16,82.55 137.79,82.55 139.06,83.82 SIDE5.32
N$91  (via drill 0.61)
  Top 0.203: v92.71,140.97 90.17,138.43 A2.A1
  Bottom 0.203: v92.71,140.97 94.61,142.88 126.36,142.88 135.25,133.99 135.25,128.91 141.6,122.56 141.6,120.65 149.22,113.03 150.5,113.03 151.76,111.76 SIDE6.10
N$92  (via drill 0.61)
  Top 0.203: v87.63,144.15 90.17,146.69 127,146.69 151.13,122.56 151.13,118.75 152.4,117.47 SIDE6.6 | v91.44,140.97 89.53,139.06 88.9,139.06 87,137.16 87,135.25 A2.B1
  Bottom 0.203: v87.63,144.15 90.81,140.97 v91.44,140.97
N$93  (via drill 0.61)
  Top 0.203: v151.13,85.09 153.03,85.09 154.31,86.36 154.31,111.76 152.4,113.67 SIDE6.8 | v135.25,81.28 135.25,93.34 v134.62,93.98 | v132.72,107.31 v129.54,110.49 | v90.17,121.92 87,125.09 87,127.64 A2.D1
  Bottom 0.203: v151.13,85.09 145.41,85.09 140.34,80.01 136.53,80.01 v135.25,81.28 | v134.62,93.98 132.72,95.89 v132.72,107.31 | v129.54,110.49 129.54,113.67 128.91,114.3 128.91,124.46 127.64,125.73 126.36,125.73 125.73,126.36 125.73,127.64 125.09,128.27 120.02,128.27 114.94,133.35 106.68,133.35 99.69,126.36 94.61,126.36 v90.17,121.92
N$94  (via drill 0.61)
  Top 0.203: v142.24,110.49 v138.43,110.49
  Bottom 0.203: v142.24,110.49 150.5,110.49 151.76,109.22 SIDE6.12 | v138.43,110.49 136.53,110.49 132.72,114.3 132.72,131.44 128.27,135.89 128.27,137.79 125.73,140.34 95.89,140.34 88.27,132.72 88.27,127 89.53,125.73 A2.E1
N$95  (via drill 0.61)
  Top 0.203: v80.01,118.11 83.19,121.28 86.36,121.28 A2.F1 | v76.83,121.28 73.03,125.09 73.03,127 72.39,127.64 72.39,132.08 64.77,139.7 v64.14,139.7 | v69.22,140.97 70.48,140.97 v74.93,136.53
  Bottom 0.203: v76.83,121.28 v80.01,118.11 | v64.14,139.7 64.14,141.6 65.41,142.88 67.94,142.88 69.22,141.6 v69.22,140.97 | v74.93,136.53 74.93,137.79 83.82,146.69 130.18,146.69 154.94,121.92 154.94,102.23 153.03,100.33 151.76,100.33 151.13,100.97 151.13,102.23 151.76,102.87 153.03,102.87 153.67,103.5 153.67,104.78 152.4,106.05 SIDE6.14
N$96  (via drill 0.61)
  Top 0.203: v100.97,91.44 94.61,97.79 94.61,106.68 95.89,107.95 95.89,109.86 90.17,115.57 90.17,118.11 A2.H1 | v111.12,91.44 118.11,91.44 121.28,94.61 129.54,94.61 v135.25,100.33 | v146.69,100.33 v138.43,100.33
  Bottom 0.203: v100.97,91.44 102.23,90.17 109.86,90.17 v111.12,91.44 | v138.43,100.33 v135.25,100.33 | v146.69,100.33 149.22,102.87 150.5,102.87 151.76,104.14 SIDE6.16
N$97  (via drill 0.61)
  Top 0.203: v84.45,141.6 86.36,141.6 90.81,146.05 125.73,146.05 147.32,124.46 147.32,109.86 149.22,107.95 153.03,107.95 153.67,107.31 153.67,100.97 152.4,99.69 SIDE6.20
  Bottom 0.203: v84.45,141.6 81.28,138.43 81.28,135.89 81.92,135.25 81.92,123.83 81.28,123.19 81.92,122.56 81.92,111.76 82.55,111.12 84.45,111.12 86.36,113.03 86.36,114.94 A2.J1
N$98  (via drill 0.61)
  Top 0.203: v80.01,119.38 80.64,119.38 84.45,123.19 87.63,123.19 88.27,122.56 88.27,118.11 89.53,116.84 89.53,113.03 A2.K1
  Bottom 0.203: v80.01,119.38 75.56,123.83 75.56,130.18 74.93,130.81 74.93,133.35 82.55,140.97 82.55,141.6 87,146.05 130.18,146.05 154.31,121.92 154.31,102.87 153.03,101.6 SIDE6.18
N$99  (via drill 0.61)
  Top 0.203: v123.19,85.09 v127,81.28 | v109.86,85.09 98.42,85.09 97.79,84.45 95.25,84.45 89.53,90.17 v89.53,91.44 | v88.27,99.06 88.27,107.31 87,108.58 A2.L1
  Bottom 0.203: v127,81.28 129.54,78.74 152.4,78.74 154.31,80.64 154.31,91.44 152.4,93.34 SIDE6.24 | v109.86,85.09 v123.19,85.09 | v89.53,91.44 88.27,92.71 v88.27,99.06
N$100  (via drill 0.61)
  Top 0.203: v133.99,88.9 v133.99,81.28 | v128.27,90.81 126.36,90.81 125.09,92.08 v123.83,92.08 | v119.38,98.42 v121.28,96.52 | v107.31,97.79 104.78,100.33 104.78,100.97 102.23,103.5 v100.97,103.5
  Bottom 0.203: v133.99,81.28 135.89,79.38 152.4,79.38 153.67,80.64 153.67,87 152.4,88.27 SIDE6.28 | v133.99,88.9 130.18,88.9 v128.27,90.81 | v123.83,92.08 123.83,93.98 v121.28,96.52 | v119.38,98.42 116.2,95.25 110.49,95.25 107.95,97.79 v107.31,97.79 | v100.97,103.5 100.33,104.14 91.44,104.14 90.17,105.41 A2.M1
N$101  (via drill 0.61)
  Top 0.203: v133.99,75.56 132.72,76.83 128.91,76.83 128.27,76.2 104.78,76.2 99.06,81.92 92.08,81.92 88.27,85.72 88.27,90.81 v83.82,95.25
  Bottom 0.203: v133.99,75.56 149.86,75.56 154.94,80.64 154.94,93.34 152.4,95.89 SIDE6.22 | v83.82,95.25 83.82,97.79 86.36,100.33 86.36,102.23 A2.N1
N$102  (via drill 0.61)
  Top 0.203: v101.6,97.79 v105.41,93.98 | v121.28,92.08 122.56,93.34 130.81,93.34 135.25,97.79 140.34,97.79 v146.05,92.08
  Bottom 0.203: v101.6,97.79 98.42,97.79 97.16,96.52 95.89,96.52 93.34,99.06 90.17,99.06 A2.P1 | v105.41,93.98 109.86,93.98 111.76,92.08 v121.28,92.08 | v146.05,92.08 146.05,90.81 149.22,87.63 150.5,87.63 151.76,86.36 SIDE6.30
N$103  (via drill 0.61)
  Top 0.203: v125.73,89.53 115.57,89.53 114.94,90.17 108.58,90.17 v107.31,91.44 | v102.23,91.44 96.52,97.16 v96.52,97.79
  Bottom 0.203: v125.73,89.53 128.27,92.08 130.18,90.17 140.34,90.17 143.51,93.34 146.05,93.34 146.69,92.71 150.5,92.71 151.76,91.44 SIDE6.26 | v102.23,91.44 v107.31,91.44 | v96.52,97.79 95.25,97.79 92.08,100.97 88.9,100.97 87,99.06 87,97.16 A2.R1
N$104  (via drill 0.61)
  Top 0.203: v90.17,97.79 91.44,99.06 v91.44,102.23 | v85.09,97.79 80.64,93.34 80.64,92.08 81.92,90.81 81.92,80.01 93.34,68.58 94.61,68.58 95.89,69.85 100.33,69.85 106.05,75.56 v132.72,75.56 | v147.32,74.3 153.67,80.64 153.67,81.92 152.4,83.19 SIDE6.32
  Bottom 0.203: v90.17,97.79 90.17,93.98 A2.S1 | v91.44,102.23 89.53,102.23 v85.09,97.79 | v132.72,75.56 133.99,74.3 v147.32,74.3
N$105  (via drill 0.61)
  Top 0.203: v147.32,76.83 151.76,81.28 SIDE6.34 | v125.73,81.28 124.46,81.28 123.83,81.92 106.68,81.92 v103.5,78.74 | v102.23,77.47 102.87,77.47 104.14,76.2 104.14,74.93 99.69,70.48 95.89,70.48 90.17,76.2 v90.17,78.11
  Bottom 0.203: v147.32,76.83 130.18,76.83 v125.73,81.28 | v102.23,77.47 v103.5,78.74 | v90.17,78.11 83.82,78.11 78.74,83.19 78.74,84.45 83.82,89.53 86.36,89.53 A2.T1
N$106  (via drill 0.61)
  Top 0.203: v89.53,83.19 89.53,78.74 88.9,78.11 88.9,75.56 93.98,70.48 v93.98,69.85 | v121.28,79.38 137.16,79.38 138.43,80.64 138.43,89.53 139.06,90.17 145.41,90.17 148.59,93.34 148.59,104.78 149.22,105.41 v151.13,105.41
  Bottom 0.203: v89.53,83.19 89.53,86.36 A2.U1 | v93.98,69.85 94.61,69.85 95.25,69.22 99.06,69.22 108.58,78.74 109.86,78.74 111.76,80.64 120.02,80.64 v121.28,79.38 | v151.13,105.41 151.13,107.31 151.76,107.95 153.03,107.95 153.67,108.58 153.67,117.47 152.4,118.75 SIDE6.4
N$107  (via drill 0.61)
  Top 0.203: v81.92,92.71 86.36,88.27 86.36,84.45 A2.V1 | v86.36,106.05 84.45,107.95 79.38,107.95 78.74,108.58 v78.74,125.73
  Bottom 0.203: v81.92,92.71 81.92,95.25 82.55,95.89 82.55,98.42 81.92,99.06 81.92,101.6 v86.36,106.05 | v78.74,125.73 78.74,127.64 75.56,130.81 75.56,133.35 83.19,140.97 83.19,141.6 87,145.41 128.27,145.41 151.76,121.92 SIDE6.2
N$108  (via drill 0.61)
  Top 0.203: SIDE6.33 149.86,81.92 149.86,83.19 SIDE6.31 149.86,84.45 149.86,85.72 SIDE6.29 149.86,87 149.86,88.27 SIDE6.27 149.86,89.53 149.86,90.81 SIDE6.25 149.86,92.08 149.86,93.34 SIDE6.23 149.86,94.61 149.86,95.89 SIDE6.21 149.86,97.16 149.86,98.42 SIDE6.19 149.86,99.69 149.86,100.97 SIDE6.17 149.86,102.23 149.86,103.5 SIDE6.15 | v135.25,109.22 133.99,109.22 128.91,114.3 130.81,116.2 130.81,136.53 127.64,139.7 115.57,139.7 113.67,141.6 95.89,141.6 92.71,138.43 92.71,137.79 90.17,135.25 90.17,132.08 A2.C1 | v138.43,107.95 138.43,106.05 139.06,105.41 147.96,105.41 149.22,106.68 SIDE6.13 | SIDE6.11 149.86,109.86 149.86,111.12 SIDE6.9 149.86,112.39 149.86,113.67 SIDE6.7 149.86,114.94 149.86,116.2 SIDE6.5 149.86,117.47 149.86,118.75 SIDE6.3 149.86,120.02 149.86,121.28 SIDE6.1
  Bottom 0.203: SIDE6.15 149.86,104.78 149.86,106.05 SIDE6.13 149.86,107.31 149.86,108.58 SIDE6.11 | v135.25,109.22 136.53,107.95 v138.43,107.95
N$109  (via drill 0.61)
  Top 0.203: SIDE7.31 5.08,84.45 5.08,85.72 SIDE7.29 5.08,87 5.08,88.27 SIDE7.27 5.08,89.53 5.08,90.81 SIDE7.25 5.08,92.08 5.08,93.34 SIDE7.23 5.08,94.61 5.08,95.89 SIDE7.21 5.08,97.16 5.08,98.42 SIDE7.19 | SIDE7.17 5.08,102.23 5.08,103.5 SIDE7.15 5.08,104.78 5.08,106.05 SIDE7.13 5.08,107.31 5.08,108.58 SIDE7.11 5.08,109.86 5.08,111.12 SIDE7.9 5.08,112.39 5.08,113.67 SIDE7.7 5.08,114.94 5.08,116.2 SIDE7.5 5.08,117.47 5.08,118.75 SIDE7.3 5.08,120.02 5.08,121.28 SIDE7.1 | v62.23,147.32 v67.94,141.6
  Bottom 0.203: SIDE7.33 5.08,81.92 5.08,83.19 SIDE7.31 | SIDE7.17 5.08,100.97 5.08,99.69 SIDE7.19 | v67.94,141.6 67.94,138.43 70.48,135.89 70.48,132.08 A3.C2 | v62.23,147.32 32.38,147.32 8.26,123.19 6.99,123.19 5.71,121.92 SIDE7.1
N$110
  Bottom 0.203: SIDE7.2 8.26,121.92 9.53,121.92 33.66,146.05 60.96,146.05 63.5,143.51 67.94,143.51 70.48,140.97 70.48,138.43 A3.A2
N$111  (via drill 0.61)
  Top 0.203: v15.24,126.36 8.26,119.38 SIDE7.4
  Bottom 0.203: v15.24,126.36 17.14,126.36 31.75,140.97 43.18,140.97 43.81,141.6 58.42,141.6 66.04,133.99 67.31,133.99 A3.B2
N$112  (via drill 0.61)
  Top 0.203: v34.29,100.33 34.29,104.78 40.01,110.49 40.01,132.72 41.91,134.62 41.91,135.25 42.55,135.89 48.26,135.89 50.8,133.35 55.88,133.35 v57.78,135.25
  Bottom 0.203: v34.29,100.33 29.84,100.33 24.77,95.25 17.14,95.25 14.61,92.71 4.45,92.71 3.81,93.34 3.81,114.94 4.45,115.57 5.71,115.57 6.99,116.84 SIDE7.6 | v57.78,135.25 64.14,128.91 67.31,128.91 A3.D2
N$113  (via drill 0.61)
  Top 0.203: v14.61,100.97 10.16,105.41 6.99,105.41 6.35,106.05 6.35,112.39 7.62,113.67 SIDE7.8 | v55.88,139.06 v59.05,139.06
  Bottom 0.203: v14.61,100.97 16.51,102.87 16.51,124.46 27.94,135.89 40.01,135.89 43.18,139.06 v55.88,139.06 | v59.05,139.06 70.48,127.64 70.48,125.73 A3.E2
N$114  (via drill 0.61)
  Top 0.203: v13.97,118.75 13.97,120.65 v24.13,130.81 | v47.62,130.81 50.16,130.81 50.8,130.18 61.59,130.18 67.31,124.46 67.31,122.56 A3.F2
  Bottom 0.203: v13.97,118.75 7.62,112.39 SIDE7.10 | v24.13,130.81 v47.62,130.81
N$115  (via drill 0.61)
  Top 0.203: v15.88,92.71 v9.53,99.06 | v45.09,87.63 50.16,87.63 50.8,88.27 v53.34,88.27 | v59.69,99.06 60.96,99.06 75.56,113.67 v75.56,114.94 | v73.66,118.75 71.12,118.75 A3.H2
  Bottom 0.203: v9.53,99.06 9.53,106.68 7.62,108.58 SIDE7.12 | v15.88,92.71 15.88,88.9 17.14,87.63 v45.09,87.63 | v53.34,88.27 57.78,88.27 59.69,90.17 v59.69,99.06 | v75.56,114.94 74.93,114.3 73.03,114.3 72.39,114.94 72.39,116.2 73.66,117.47 v73.66,118.75
N$116  (via drill 0.61)
  Top 0.203: v62.23,146.05 26.67,146.05 6.35,125.73 6.35,118.75 6.99,118.11 8.26,118.11 8.89,117.47 8.89,108.58 7.62,107.31 SIDE7.14 | v71.12,128.91 71.12,127 72.39,125.73 72.39,123.19 67.94,118.75 67.94,116.2 A3.J2
  Bottom 0.203: v62.23,146.05 66.04,146.05 72.39,139.7 72.39,136.53 71.12,135.25 71.12,133.35 72.39,132.08 72.39,130.18 v71.12,128.91
N$117  (via drill 0.61)
  Top 0.203: v19.05,123.19 17.14,123.19 16.51,122.56 16.51,100.97 17.14,100.33 15.88,99.06 15.24,99.06 10.16,104.14 8.26,104.14 SIDE7.16 | v31.75,123.19 33.66,123.19 38.73,118.11 v38.73,114.3 | v41.27,111.76 42.55,110.49 46.35,110.49 50.16,114.3 64.77,114.3 67.31,111.76 70.48,111.76 A3.K2
  Bottom 0.203: v19.05,123.19 v31.75,123.19 | v38.73,114.3 v41.27,111.76
N$118  (via drill 0.61)
  Top 0.203: v3.81,123.83 3.81,100.97 4.45,100.33 5.71,100.33 6.99,101.6 SIDE7.18 | v26.67,144.78 v33.66,144.78 | v35.56,142.88 64.14,142.88 v65.41,141.6 | v66.04,135.25 66.04,127 v68.58,124.46 | v64.77,109.86 67.31,109.86 A3.L2
  Bottom 0.203: v3.81,123.83 24.77,144.78 v26.67,144.78 | v33.66,144.78 v35.56,142.88 | v65.41,141.6 65.41,139.06 66.04,138.43 v66.04,135.25 | v68.58,124.46 67.31,123.19 66.67,123.19 66.04,122.56 66.04,111.12 v64.77,109.86
N$119  (via drill 0.61)
  Top 0.203: v11.43,87.63 11.43,95.89 8.26,99.06 SIDE7.20 | v11.43,81.92 11.43,78.11 v24.13,65.41 | v34.29,67.31 v41.91,67.31 | v47.62,67.31 50.16,64.77 v52.7,64.77 | v66.67,66.04 66.67,67.31 78.74,79.38 78.74,90.81 79.38,91.44 79.38,95.25 78.74,95.89 78.74,106.68 v76.83,108.58
  Bottom 0.203: v11.43,81.92 v11.43,87.63 | v24.13,65.41 27.94,65.41 29.84,67.31 v34.29,67.31 | v41.91,67.31 v47.62,67.31 | v52.7,64.77 57.78,59.69 60.33,59.69 v66.67,66.04 | v76.83,108.58 75.56,108.58 73.66,106.68 71.12,106.68 A3.M2
N$120  (via drill 0.61)
  Top 0.203: v14.61,123.19 27.3,135.89 27.3,137.16 34.29,144.15 64.14,144.15 v66.67,141.6 | v69.22,130.81 v69.22,126.36 | v62.87,117.47 v67.31,113.03
  Bottom 0.203: v14.61,123.19 15.24,122.56 15.24,103.5 8.26,96.52 SIDE7.22 | v66.67,141.6 66.67,137.79 69.22,135.25 v69.22,130.81 | v69.22,126.36 62.87,120.02 v62.87,117.47 | v67.31,113.03 67.31,111.12 66.04,109.86 66.04,104.78 67.31,103.5 A3.N2
N$121  (via drill 0.61)
  Top 0.203: v66.04,88.27 69.22,85.09 69.22,81.92 67.94,80.64 67.31,81.28 57.78,81.28 50.8,74.3 22.86,74.3 9.53,87.63 6.99,87.63 6.35,88.27 6.35,92.08 7.62,93.34 SIDE7.24 | v66.04,97.16 67.94,99.06 70.48,99.06 A3.P2
  Bottom 0.203: v66.04,88.27 v66.04,97.16
N$122  (via drill 0.61)
  Top 0.203: v15.88,86.36 11.43,86.36 10.16,87.63 10.16,88.27 7.62,90.81 SIDE7.26 | v31.75,85.09 36.2,89.53 53.34,89.53 54.61,88.27 62.87,88.27 v67.31,92.71
  Bottom 0.203: v15.88,86.36 17.14,85.09 v31.75,85.09 | v67.31,92.71 67.31,95.89 A3.R2
N$123  (via drill 0.61)
  Top 0.203: v9.53,91.44 v9.53,96.52
  Bottom 0.203: v9.53,91.44 7.62,89.53 SIDE7.28 | v9.53,96.52 13.34,100.33 13.34,100.97 15.88,103.5 15.88,124.46 31.11,139.7 42.55,139.7 43.81,140.97 58.42,140.97 67.94,131.44 67.94,130.81 71.75,127 71.75,126.36 72.39,125.73 72.39,116.84 68.58,113.03 68.58,110.49 69.22,109.86 69.22,99.06 70.48,97.79 70.48,93.98 A3.S2
N$124  (via drill 0.61)
  Top 0.203: v73.03,140.97 64.77,149.22 27.94,149.22 2.54,123.83 2.54,84.45 4.45,82.55 5.71,82.55 6.35,83.19 6.35,84.45 7.62,85.72 SIDE7.30 | v76.83,116.84 76.83,114.3 75.56,113.03 75.56,89.53 74.93,88.9 68.58,88.9 67.94,89.53 A3.T2
  Bottom 0.203: v73.03,140.97 73.03,136.53 71.75,135.25 71.75,133.35 73.03,132.08 73.03,129.54 72.39,128.91 72.39,126.36 75.56,123.19 75.56,118.11 v76.83,116.84
N$125  (via drill 0.61)
  Top 0.203: v27.94,77.47 30.48,74.93 50.8,74.93 57.78,81.92 v67.94,81.92
  Bottom 0.203: v27.94,77.47 26.04,79.38 12.06,79.38 10.16,81.28 8.26,81.28 SIDE7.34 | v67.94,81.92 70.48,84.45 70.48,86.36 A3.U2
N$126  (via drill 0.61)
  Top 0.203: v40.64,80.01 53.34,80.01 55.88,82.55 66.67,82.55 67.31,83.19 A3.V2
  Bottom 0.203: v40.64,80.01 12.06,80.01 8.26,83.82 SIDE7.32
N$127  (via drill 0.61)
  Top 0.203: v19.05,97.79 19.05,109.86 20.32,111.12 SIDE8.10 | v66.67,148.59 76.83,138.43 A3.A1
  Bottom 0.203: v19.05,97.79 12.06,97.79 9.53,95.25 6.99,95.25 6.35,95.89 6.35,114.94 6.99,115.57 8.26,115.57 8.89,116.2 8.89,120.02 8.26,120.65 4.45,120.65 3.81,121.28 3.81,122.56 10.16,128.91 13.34,128.91 33.02,148.59 v66.67,148.59
N$128
  Top 0.203: SIDE8.6 20.32,117.47 27.94,125.09 27.94,137.16 32.38,141.6 64.14,141.6 70.48,135.25 73.66,135.25 A3.B1
N$129  (via drill 0.61)
  Top 0.203: v24.77,105.41 24.77,109.22 20.32,113.67 SIDE8.8 | v15.88,100.33 15.88,114.3 12.7,117.47 12.7,122.56 26.67,136.53 v26.67,143.51
  Bottom 0.203: v24.77,105.41 24.77,104.14 20.95,100.33 v15.88,100.33 | v26.67,143.51 33.02,149.86 67.94,149.86 74.3,143.51 74.3,137.16 72.39,135.25 72.39,133.35 73.66,132.08 73.66,128.91 A3.D1
N$130  (via drill 0.61)
  Top 0.203: v41.91,107.95 41.91,103.5 33.66,95.25 29.84,95.25 29.21,95.89 29.21,99.69 20.32,108.58 SIDE8.12 | v48.26,107.95 49.53,109.22 52.7,109.22 53.98,107.95 68.58,107.95 73.03,112.39 73.03,114.3 72.39,114.94 72.39,116.2 73.03,116.84 v75.56,116.84
  Bottom 0.203: v41.91,107.95 v48.26,107.95 | v75.56,116.84 76.83,115.57 78.11,115.57 79.38,116.84 80.01,116.84 81.28,118.11 81.28,119.38 80.01,120.65 79.38,120.65 77.47,122.56 77.47,124.46 A3.E1
N$131  (via drill 0.61)
  Top 0.203: v28.57,115.57 28.57,137.16 32.38,140.97 64.14,140.97 75.56,129.54 75.56,123.83 78.11,121.28 76.83,120.02 75.56,120.02 74.3,121.28 A3.F1
  Bottom 0.203: v28.57,115.57 20.32,107.31 SIDE8.14
N$132  (via drill 0.61)
  Top 0.203: v41.27,117.47 41.27,119.38 42.55,120.65 66.04,120.65 v67.31,119.38 | v69.85,116.84 72.39,116.84 73.03,117.47 74.93,117.47 76.83,119.38 A3.H1
  Bottom 0.203: v41.27,117.47 40.64,118.11 19.68,118.11 19.05,117.47 19.05,106.05 20.32,104.78 SIDE8.16 | v67.31,119.38 v69.85,116.84
N$133  (via drill 0.61)
  Top 0.203: v31.75,110.49 v38.73,110.49 | v49.53,107.95 53.34,107.95 53.98,107.31 68.58,107.31 73.66,112.39 73.66,114.94 A3.J1
  Bottom 0.203: v31.75,110.49 29.84,110.49 26.67,107.31 26.67,104.78 20.95,99.06 SIDE8.20 | v38.73,110.49 46.99,110.49 v49.53,107.95
N$134  (via drill 0.61)
  Top 0.203: v48.9,111.76 56.52,111.76 57.15,111.12 69.22,111.12 v69.85,110.49
  Bottom 0.203: v48.9,111.76 47.62,113.03 42.55,113.03 40.01,115.57 29.84,115.57 29.21,114.94 29.21,111.12 20.32,102.23 SIDE8.18 | v69.85,110.49 75.56,110.49 76.83,111.76 A3.K1
N$135  (via drill 0.61)
  Top 0.203: v40.64,93.98 42.55,93.98 44.45,95.89 44.45,99.69 45.09,100.33 53.34,100.33 58.42,95.25 62.23,95.25 73.66,106.68 73.66,108.58 A3.L1
  Bottom 0.203: v40.64,93.98 20.95,93.98 SIDE8.24
N$136  (via drill 0.61)
  Top 0.203: v62.23,67.94 63.5,66.67 65.41,66.67 75.56,76.83 v75.56,87
  Bottom 0.203: v62.23,67.94 60.96,69.22 57.15,69.22 52.7,73.66 52.7,81.28 45.09,88.9 20.95,88.9 SIDE8.28 | v75.56,87 75.56,104.14 76.83,105.41 A3.M1
N$137  (via drill 0.61)
  Top 0.203: v53.98,92.71 31.75,92.71 27.94,96.52 20.95,96.52 SIDE8.22 | v55.88,94.61 62.23,94.61 69.85,102.23 73.66,102.23 A3.N1
  Bottom 0.203: v53.98,92.71 v55.88,94.61
N$138  (via drill 0.61)
  Top 0.203: v50.16,71.75 58.42,71.75 59.05,71.12 61.59,71.12 71.75,81.28 71.75,84.45 78.74,91.44 78.74,95.25 77.47,96.52 77.47,99.06 A3.P1
  Bottom 0.203: v50.16,71.75 35.56,86.36 20.95,86.36 SIDE8.30
N$139  (via drill 0.61)
  Top 0.203: v67.31,88.27 69.85,85.72 v71.75,85.72
  Bottom 0.203: v67.31,88.27 67.31,87.63 64.14,84.45 62.87,84.45 62.23,85.09 59.05,85.09 56.52,82.55 52.7,82.55 43.81,91.44 20.95,91.44 SIDE8.26 | v71.75,85.72 72.39,86.36 72.39,94.61 73.66,95.89 A3.R1
N$140  (via drill 0.61)
  Top 0.203: v66.04,84.45 62.87,84.45 61.59,85.72 33.66,85.72 31.75,83.82 20.95,83.82 SIDE8.32 | v69.22,87.63 69.85,88.27 74.93,88.27 76.83,90.17 76.83,92.71 A3.S1
  Bottom 0.203: v66.04,84.45 v69.22,87.63
N$141  (via drill 0.61)
  Top 0.203: v56.52,89.53 56.52,90.81 55.88,91.44 53.98,91.44 52.7,90.17 19.68,90.17 19.05,89.53 19.05,83.19 20.32,81.92 SIDE8.34 | v62.87,85.72 62.87,87.63 66.67,91.44 73.03,91.44 73.66,90.81 A3.T1
  Bottom 0.203: v56.52,89.53 55.88,88.9 53.98,88.9 53.34,89.53 52.07,88.27 54.61,85.72 v62.87,85.72
N$142  (via drill 0.61)
  Top 0.203: v28.57,106.68 28.57,107.95 20.95,115.57 19.68,115.57 19.05,116.2 19.05,117.47 20.32,118.75 SIDE8.4 | v57.78,89.53 59.69,89.53 60.33,88.9 62.23,88.9 v72.39,99.06
  Bottom 0.203: v28.57,106.68 29.84,105.41 33.66,105.41 41.91,97.16 41.91,95.89 46.35,91.44 55.88,91.44 v57.78,89.53 | v72.39,99.06 72.39,103.5 76.2,107.31 78.11,107.31 78.74,106.68 78.74,91.44 77.47,90.17 77.47,87.63 A3.U1
N$143  (via drill 0.61)
  Top 0.203: v71.75,113.67 68.58,116.84 68.58,118.11 v69.22,118.75 | v69.22,121.28 68.58,120.65 66.67,120.65 v64.14,123.19 | v26.04,128.27 20.32,122.56 SIDE8.2
  Bottom 0.203: v71.75,113.67 78.11,113.67 81.92,109.86 81.92,102.23 81.28,101.6 81.28,99.06 81.92,98.42 81.92,95.89 81.28,95.25 81.28,93.34 78.74,90.81 78.74,86.36 76.83,84.45 74.3,84.45 A3.V1 | v69.22,121.28 v69.22,118.75 | v64.14,123.19 56.52,123.19 55.24,124.46 50.8,124.46 48.9,126.36 48.9,127 47.62,128.27 v26.04,128.27
N$144  (via drill 0.61)
  Top 0.203: SIDE8.1 17.78,121.28 17.78,120.02 SIDE8.3 17.78,118.75 17.78,117.47 SIDE8.5 17.78,116.2 17.78,114.94 SIDE8.7 17.78,113.67 17.78,112.39 SIDE8.9 17.78,111.12 17.78,109.86 SIDE8.11 17.78,108.58 17.78,107.31 SIDE8.13 17.78,106.05 17.78,104.78 SIDE8.15 17.78,103.5 17.78,102.23 SIDE8.17 17.78,100.97 17.78,99.69 SIDE8.19 17.78,98.42 17.78,97.16 SIDE8.21 17.78,95.89 17.78,94.61 SIDE8.23 17.78,93.34 17.78,92.08 SIDE8.25 17.78,90.81 17.78,89.53 SIDE8.27 17.78,88.27 17.78,87 SIDE8.29 17.78,85.72 17.78,84.45 SIDE8.31 17.78,83.19 17.78,81.92 SIDE8.33 17.78,80.64 v20.32,78.11 | v27.3,147.32 36.83,147.32 38.1,148.59 64.14,148.59 76.83,135.89 76.83,132.08 A3.C1
  Bottom 0.203: v27.3,147.32 26.04,147.32 2.54,123.83 2.54,81.92 6.35,78.11 v20.32,78.11
N$145  (via drill 0.61)
  Top 0.203: SIDE9.33 30.48,97.16 30.48,98.42 SIDE9.31 30.48,99.69 30.48,100.97 SIDE9.29 30.48,102.23 30.48,103.5 SIDE9.27 30.48,104.78 30.48,106.05 SIDE9.25 30.48,107.31 30.48,108.58 SIDE9.23 30.48,109.86 30.48,111.12 SIDE9.21 30.48,112.39 30.48,113.67 SIDE9.19 30.48,114.94 30.48,116.2 SIDE9.17 30.48,117.47 30.48,118.75 SIDE9.15 30.48,120.02 30.48,121.28 SIDE9.13 30.48,122.56 30.48,123.83 SIDE9.11 30.48,125.09 30.48,126.36 SIDE9.9 30.48,127.64 30.48,128.91 SIDE9.7 30.48,130.18 30.48,131.44 SIDE9.5 30.48,132.72 30.48,133.99 SIDE9.3 30.48,135.25 30.48,136.53 SIDE9.1 31.11,137.16 33.02,139.06 46.99,139.06 v48.9,137.16
  Bottom 0.203: v48.9,137.16 53.98,132.08 57.78,132.08 A4.C2
N$146
  Bottom 0.203: SIDE9.2 33.66,137.16 40.64,137.16 43.81,140.34 55.88,140.34 57.78,138.43 A4.A2
N$147
  Top 0.203: SIDE9.4 33.66,134.62 38.73,134.62 42.55,138.43 46.35,138.43 49.53,135.25 54.61,135.25 A4.B2
N$148
  Bottom 0.203: A4.D2 54.61,128.91 47.62,135.89 40.64,135.89 36.83,132.08 33.66,132.08 SIDE9.6
N$149  (via drill 0.61)
  Top 0.203: v49.53,128.27 52.07,125.73 57.78,125.73 A4.E2 | v39.37,133.35 37.47,133.35 33.66,129.54 SIDE9.8
  Bottom 0.203: v49.53,128.27 49.53,130.18 46.35,133.35 v39.37,133.35
N$150
  Bottom 0.203: A4.F2 54.61,122.56 49.53,122.56 46.35,125.73 34.92,125.73 33.66,127 SIDE9.10
N$151
  Bottom 0.203: A4.H2 57.78,119.38 50.16,119.38 46.35,123.19 34.92,123.19 33.66,124.46 SIDE9.12
N$152
  Bottom 0.203: A4.J2 54.61,116.2 50.8,116.2 46.35,120.65 42.55,120.65 41.27,121.92 33.66,121.92 SIDE9.14
N$153
  Bottom 0.203: A4.K2 57.78,113.03 51.44,113.03 46.35,118.11 42.55,118.11 40.01,120.65 34.92,120.65 33.66,119.38 SIDE9.16
N$154
  Bottom 0.203: A4.L2 54.61,109.86 52.07,109.86 46.35,115.57 40.64,115.57 39.37,116.84 33.66,116.84 SIDE9.18
N$155  (via drill 0.61)
  Top 0.203: v53.34,105.41 57.78,105.41 A4.M2
  Bottom 0.203: v53.34,105.41 42.55,105.41 33.66,114.3 SIDE9.20
N$156
  Bottom 0.203: SIDE9.22 33.66,111.76 42.55,102.87 54.61,102.87 A4.N2
N$157  (via drill 0.61)
  Top 0.203: v41.27,101.6 42.55,102.87 52.7,102.87 55.24,100.33 57.78,100.33 A4.P2
  Bottom 0.203: v41.27,101.6 33.66,109.22 SIDE9.24
N$158
  Bottom 0.203: SIDE9.26 33.66,106.68 42.55,97.79 53.98,97.79 54.61,97.16 A4.R2
N$159
  Bottom 0.203: A4.S2 57.78,93.98 57.78,95.89 53.34,100.33 41.27,100.33 33.66,107.95 28.57,107.95 27.3,106.68 27.3,105.41 29.84,102.87 31.11,102.87 32.38,104.14 SIDE9.28
N$160
  Bottom 0.203: SIDE9.30 33.66,101.6 35.56,101.6 46.35,90.81 54.61,90.81 A4.T2
N$161  (via drill 0.61)
  Top 0.203: v50.8,87 57.78,87 A4.U2
  Bottom 0.203: v50.8,87 50.16,87.63 48.26,87.63 39.37,96.52 33.66,96.52 SIDE9.34
N$162
  Bottom 0.203: SIDE9.32 33.66,99.06 37.47,99.06 47.62,88.9 50.16,88.9 54.61,84.45 A4.V2
N$163  (via drill 0.61)
  Top 0.203: v50.8,125.73 47.62,125.73 46.35,127 SIDE10.10 | v50.8,131.44 55.88,131.44 61.59,137.16 64.14,137.16 A4.A1
  Bottom 0.203: v50.8,125.73 v50.8,131.44
N$164  (via drill 0.61)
